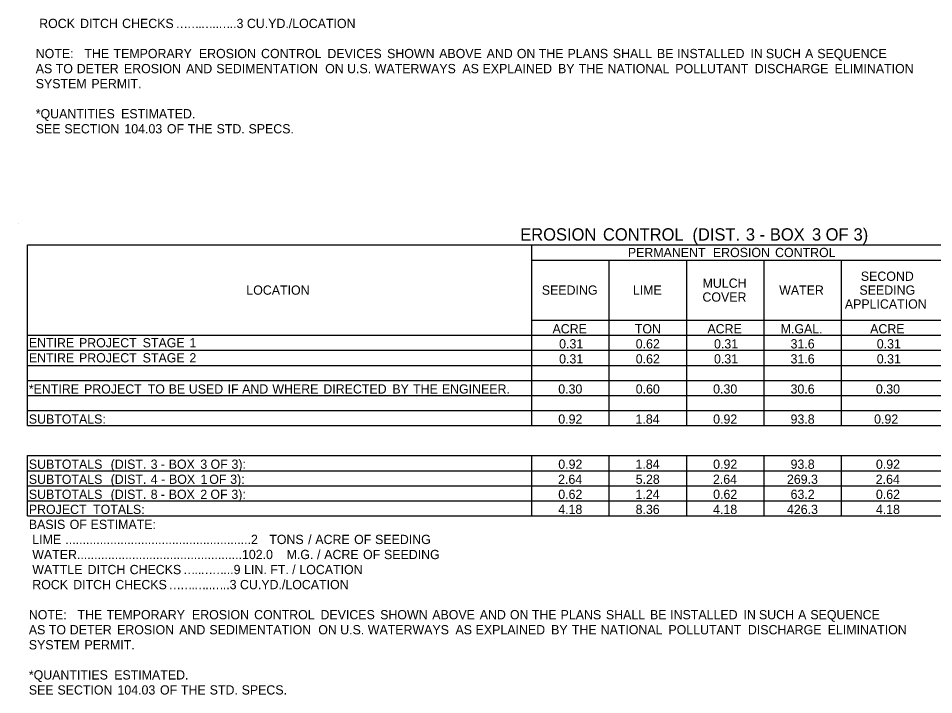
# Model space of a CAD drawing. Extents: x 540541 to 1930787, y -1948574 to 596640.
# Drawn here: x 546405 to 546999, y -1948502 to -1948064 of the extents above; entities that cross this region are included whole.
import ezdxf

# ---------------------------------------------------------------- set-up
doc = ezdxf.new("R2010")
doc.units = 0
doc.layers.add('Default', color=7, linetype='Continuous')
doc.layers.add('R_Border', color=7, linetype='Continuous')

msp = doc.modelspace()

# ---------------------------------------------------------------- linework, layer by layer
at = {"layer": 'Default'}
for p, q in [((546411.17, -1948210.49), (547281.84, -1948210.49)), ((546411.17, -1948327.49), (546411.17, -1948210.49)), ((546411.17, -1948327.49), (546411.17, -1948210.49)), ((546738.28, -1948327.49), (546738.28, -1948210.49)), ((546738.28, -1948220.24), (547281.84, -1948220.24)), ((546788.49, -1948327.49), (546788.49, -1948220.24)), ((546838.7, -1948327.49), (546838.7, -1948220.24)), ((546888.92, -1948327.49), (546888.92, -1948220.24)), ((546939.13, -1948327.49), (546939.13, -1948220.24)), ((546738.28, -1948259.24), (547221.88, -1948259.24)), ((546788.49, -1948327.49), (546788.49, -1948259.24)), ((546838.7, -1948317.74), (546838.7, -1948259.24)), ((546888.92, -1948317.74), (546888.92, -1948259.24)), ((546939.13, -1948317.74), (546939.13, -1948259.24)), ((546411.17, -1948268.99), (547281.84, -1948268.99)), ((546411.17, -1948278.74), (547281.84, -1948278.74)), ((546411.17, -1948288.49), (547281.84, -1948288.49)), ((546411.17, -1948298.24), (547281.84, -1948298.24)), ((546411.17, -1948307.99), (547281.84, -1948307.99)), ((546411.17, -1948317.74), (547121.94, -1948317.74)), ((546738.28, -1948327.49), (546738.28, -1948317.74)), ((546788.49, -1948317.74), (546999.58, -1948317.74)), ((546411.17, -1948327.49), (547281.84, -1948327.49)), ((546411.17, -1948346.99), (547281.84, -1948346.99)), ((546411.17, -1948346.99), (547281.84, -1948346.99)), ((546411.17, -1948385.99), (546411.17, -1948346.99)), ((546411.17, -1948385.99), (546411.17, -1948346.99)), ((546738.28, -1948385.99), (546738.28, -1948346.99)), ((546738.28, -1948385.99), (546738.28, -1948346.99)), ((546788.49, -1948385.99), (546788.49, -1948346.99)), ((546838.7, -1948385.99), (546838.7, -1948346.99)), ((546888.92, -1948385.99), (546888.92, -1948346.99)), ((546939.13, -1948385.99), (546939.13, -1948346.99)), ((546411.17, -1948356.74), (547281.84, -1948356.74)), ((546788.49, -1948385.99), (546788.49, -1948356.74)), ((546838.7, -1948385.99), (546838.7, -1948356.74)), ((546888.92, -1948385.99), (546888.92, -1948356.74)), ((546939.13, -1948385.99), (546939.13, -1948356.74)), ((546411.17, -1948366.49), (547281.84, -1948366.49)), ((546411.17, -1948376.24), (547281.84, -1948376.24)), ((546411.17, -1948385.99), (547281.84, -1948385.99))]:
    msp.add_line(p, q, dxfattribs=at)
at = {"layer": 'R_Border'}
msp.add_line((546405.32, -1948196.84), (546405.32, -1948196.84), dxfattribs=at)

# ---------------------------------------------------------------- texts
at = {"layer": 'Default'}
for s, height, p in [(' ROCK', 6, (546416.62, -1948069.96)), (' DITCH', 6, (546443.15, -1948069.96)), (' CHECKS', 6, (546470.41, -1948069.96)), ('..3', 6, (546542.36, -1948069.96)), (' CU.YD./LOCATION', 6, (546551.3, -1948069.96)), ('…', 6, (546507.25, -1948069.96)), ('…', 6, (546514.65, -1948069.96)), ('.', 6, (546522.05, -1948069.96)), ('…', 6, (546523.64, -1948069.96)), ('..', 6, (546531.04, -1948069.96)), ('…', 6, (546534.97, -1948069.96)), ('NOTE:', 6, (546416.62, -1948089.46)), ('   THE', 6, (546441.5, -1948089.46)), (' TEMPORARY', 6, (546464.81, -1948089.46)), (' EROSION', 6, (546520.18, -1948089.46)), (' CONTROL', 6, (546560.49, -1948089.46)), (' DEVICES', 6, (546603.51, -1948089.46)), (' SHOWN', 6, (546642.21, -1948089.46)), (' ABOVE', 6, (546675.98, -1948089.46)), (' AND', 6, (546706.76, -1948089.46)), (' ON', 6, (546726.34, -1948089.46)), (' THE', 6, (546740.56, -1948089.46)), (' PLANS', 6, (546759.21, -1948089.46)), (' SHALL', 6, (546788.59, -1948089.46)), (' BE', 6, (546817.18, -1948089.46)), (' INSTALLED', 6, (546830.25, -1948089.46)), (' IN', 6, (546877.78, -1948089.46)), (' SUCH', 6, (546887.81, -1948089.46)), (' A', 6, (546913.22, -1948089.46)), (' SEQUENCE', 6, (546921.15, -1948089.46)), ('AS', 6, (546416.62, -1948099.21)), (' TO', 6, (546427.36, -1948099.21)), (' DETER', 6, (546440.96, -1948099.21)), (' EROSION', 6, (546471.59, -1948099.21)), (' AND', 6, (546511.9, -1948099.21)), (' SEDIMENTATION', 6, (546531.48, -1948099.21)), (' ON', 6, (546602.06, -1948099.21)), (' U.S.', 6, (546616.28, -1948099.21)), (' WATERWAYS', 6, (546634.18, -1948099.21)), (' AS', 6, (546691.03, -1948099.21)), (' EXPLAINED', 6, (546704.11, -1948099.21)), (' BY', 6, (546753.05, -1948099.21)), (' THE', 6, (546766.5, -1948099.21)), (' NATIONAL', 6, (546785.15, -1948099.21)), (' POLLUTANT', 6, (546829.11, -1948099.21)), (' DISCHARGE', 6, (546880.65, -1948099.21)), (' ELIMINATION', 6, (546932.37, -1948099.21)), ('SYSTEM', 6, (546416.62, -1948108.96)), (' PERMIT.', 6, (546450.46, -1948108.96)), ('*QUANTITIES', 6, (546416.62, -1948128.46)), (' ESTIMATED.', 6, (546469.75, -1948128.46)), ('SEE', 6, (546416.62, -1948138.21)), (' SECTION', 6, (546432.95, -1948138.21)), (' 104.03', 6, (546471.86, -1948138.21)), (' OF', 6, (546499.43, -1948138.21)), (' THE', 6, (546513.02, -1948138.21)), (' STD.', 6, (546531.67, -1948138.21)), (' SPECS.', 6, (546552.36, -1948138.21)), ('EROSION', 8, (546730.77, -1948207.66)), (' CONTROL', 8, (546781.43, -1948207.66)), (' (DIST.', 8, (546839.47, -1948207.66)), (' 3', 8, (546874.09, -1948207.66)), (' BOX', 8, (546889.67, -1948207.66)), (' 3', 8, (546916.98, -1948207.66)), (' OF', 8, (546925.82, -1948207.66)), (' 3)', 8, (546943.93, -1948207.66)), (' -', 8, (546882.92, -1948207.66)), ('PERMANENT', 6, (546800.54, -1948218.36)), (' EROSION', 6, (546853.47, -1948218.36)), (' CONTROL', 6, (546893.79, -1948218.36)), ('MULCH', 6, (546849, -1948238.24)), ('SECOND', 6, (546951.63, -1948233.74)), ('LOCATION', 6, (546553.17, -1948242.74)), ('SEEDING', 6, (546744.77, -1948242.74)), ('LIME', 6, (546803.79, -1948242.74)), ('WATER', 6, (546898.68, -1948242.74)), ('SEEDING', 6, (546950.74, -1948242.74)), ('COVER', 6, (546848.92, -1948247.24)), ('APPLICATION', 6, (546941.28, -1948251.74)), ('ACRE', 6, (546751.71, -1948267.79)), ('TON', 6, (546805.09, -1948267.79)), ('ACRE', 6, (546852.14, -1948267.79)), ('M.GAL.', 6, (546899.64, -1948267.79)), ('ACRE', 6, (546957.68, -1948267.79)), ('ENTIRE', 6, (546412.14, -1948276.86)), (' PROJECT', 6, (546442.44, -1948276.86)), (' STAGE', 6, (546483.73, -1948276.86)), (' 1', 6, (546514.03, -1948276.86)), ('0.31', 6, (546756, -1948277.54)), ('0.62', 6, (546805.67, -1948277.54)), ('0.31', 6, (546856.43, -1948277.54)), ('31.6', 6, (546906.06, -1948277.54)), ('0.31', 6, (546961.97, -1948277.54)), ('ENTIRE', 6, (546412.14, -1948286.61)), (' PROJECT', 6, (546442.44, -1948286.61)), (' STAGE', 6, (546483.73, -1948286.61)), (' 2', 6, (546514.03, -1948286.61)), ('0.31', 6, (546756, -1948287.29)), ('0.62', 6, (546805.67, -1948287.29)), ('0.31', 6, (546856.43, -1948287.29)), ('31.6', 6, (546906.06, -1948287.29)), ('0.31', 6, (546961.97, -1948287.29)), ('*ENTIRE', 6, (546412.14, -1948306.79)), (' PROJECT', 6, (546445.7, -1948306.79)), (' TO', 6, (546486.99, -1948306.79)), (' BE', 6, (546500.59, -1948306.79)), (' USED', 6, (546513.65, -1948306.79)), (' IF', 6, (546538.83, -1948306.79)), (' AND', 6, (546548.22, -1948306.79)), (' WHERE', 6, (546567.8, -1948306.79)), (' DIRECTED', 6, (546600.89, -1948306.79)), (' BY', 6, (546645.62, -1948306.79)), (' THE', 6, (546659.07, -1948306.79)), (' ENGINEER.', 6, (546677.72, -1948306.79)), ('0.30', 6, (546755.43, -1948306.79)), ('0.60', 6, (546805.65, -1948306.79)), ('0.30', 6, (546855.86, -1948306.79)), ('30.6', 6, (546906.06, -1948306.79)), ('0.30', 6, (546961.4, -1948306.79)), ('SUBTOTALS:', 6, (546412.14, -1948326.29)), ('0.92', 6, (546755.44, -1948326.29)), ('1.84', 6, (546805.54, -1948326.29)), ('0.92', 6, (546855.87, -1948326.29)), ('93.8', 6, (546906.06, -1948326.29)), ('0.92', 6, (546960.25, -1948326.29)), ('SUBTOTALS', 6, (546412.14, -1948355.54)), (' (DIST.', 6, (546462.97, -1948355.54)), (' 3', 6, (546488.93, -1948355.54)), (' BOX', 6, (546500.62, -1948355.54)), (' 3', 6, (546521.11, -1948355.54)), (' OF', 6, (546527.73, -1948355.54)), (' 3):', 6, (546541.32, -1948355.54)), ('0.92', 6, (546755.44, -1948355.54)), ('1.84', 6, (546805.54, -1948355.54)), ('0.92', 6, (546855.87, -1948355.54)), ('93.8', 6, (546906.06, -1948355.54)), ('0.92', 6, (546961.41, -1948355.54)), (' -', 6, (546495.56, -1948355.54)), ('SUBTOTALS', 6, (546412.14, -1948365.29)), (' (DIST.', 6, (546462.97, -1948365.29)), (' 4', 6, (546488.93, -1948365.29)), (' -', 6, (546495.73, -1948365.29)), (' BOX', 6, (546500.79, -1948365.29)), (' 1', 6, (546521.28, -1948365.29)), (' OF', 6, (546526.91, -1948365.29)), (' 3):', 6, (546540.49, -1948365.29)), ('2.64', 6, (546755.33, -1948365.29)), ('5.28', 6, (546805.63, -1948365.29)), ('2.64', 6, (546855.75, -1948365.29)), ('269.3', 6, (546903.72, -1948365.29)), ('2.64', 6, (546961.3, -1948365.29)), ('SUBTOTALS', 6, (546412.14, -1948375.04)), (' (DIST.', 6, (546462.97, -1948375.04)), (' 8', 6, (546488.93, -1948375.04)), (' BOX', 6, (546500.61, -1948375.04)), (' 2', 6, (546521.09, -1948375.04)), (' OF', 6, (546527.66, -1948375.04)), (' 3):', 6, (546541.24, -1948375.04)), ('0.62', 6, (546755.44, -1948375.04)), ('1.24', 6, (546805.54, -1948375.04)), ('0.62', 6, (546855.87, -1948375.04)), ('63.2', 6, (546906.08, -1948375.04)), ('0.62', 6, (546961.41, -1948375.04)), (' -', 6, (546495.55, -1948375.04)), ('PROJECT', 6, (546412.14, -1948384.79)), (' TOTALS:', 6, (546451.57, -1948384.79)), ('4.18', 6, (546755.42, -1948384.79)), ('8.36', 6, (546805.59, -1948384.79)), ('4.18', 6, (546855.84, -1948384.79)), ('426.3', 6, (546903.72, -1948384.79)), ('4.18', 6, (546961.39, -1948384.79)), ('BASIS', 6, (546412.14, -1948394.54)), (' OF', 6, (546436.4, -1948394.54)), (' ESTIMATE:', 6, (546449.99, -1948394.54)), (' LIME', 6, (546412.14, -1948404.29)), (' ......................................................2', 6, (546433.59, -1948404.29)), (' TONS', 6, (546565.83, -1948404.29)), (' /', 6, (546591.01, -1948404.29)), (' ACRE', 6, (546595.67, -1948404.29)), (' OF', 6, (546620.84, -1948404.29)), (' SEEDING', 6, (546634.43, -1948404.29)), (' WATER................................................102.0', 6, (546412.14, -1948414.04)), (' M.G.', 6, (546577.04, -1948414.04)), (' /', 6, (546596.8, -1948414.04)), (' ACRE', 6, (546601.46, -1948414.04)), (' OF', 6, (546626.63, -1948414.04)), (' SEEDING', 6, (546640.22, -1948414.04)), (' WATTLE', 6, (546412.14, -1948423.79)), (' DITCH', 6, (546448.02, -1948423.79)), (' CHECKS', 6, (546475.29, -1948423.79)), ('…', 6, (546512.12, -1948423.79)), ('..', 6, (546519.52, -1948423.79)), ('…', 6, (546523.44, -1948423.79)), ('…', 6, (546530.84, -1948423.79)), ('...9', 6, (546538.24, -1948423.79)), (' LIN.', 6, (546549.52, -1948423.79)), (' FT.', 6, (546566.48, -1948423.79)), (' /', 6, (546580.65, -1948423.79)), (' LOCATION', 6, (546585.31, -1948423.79)), (' ROCK', 6, (546412.14, -1948433.54)), (' DITCH', 6, (546438.68, -1948433.54)), (' CHECKS', 6, (546465.94, -1948433.54)), ('..3', 6, (546537.89, -1948433.54)), (' CU.YD./LOCATION', 6, (546546.83, -1948433.54)), ('…', 6, (546502.77, -1948433.54)), ('…', 6, (546510.17, -1948433.54)), ('.', 6, (546517.57, -1948433.54)), ('…', 6, (546519.17, -1948433.54)), ('..', 6, (546526.57, -1948433.54)), ('…', 6, (546530.49, -1948433.54)), ('NOTE:', 6, (546412.14, -1948453.04)), ('   THE', 6, (546437.03, -1948453.04)), (' TEMPORARY', 6, (546460.33, -1948453.04)), (' EROSION', 6, (546515.71, -1948453.04)), (' CONTROL', 6, (546556.01, -1948453.04)), (' DEVICES', 6, (546599.03, -1948453.04)), (' SHOWN', 6, (546637.73, -1948453.04)), (' ABOVE', 6, (546671.51, -1948453.04)), (' AND', 6, (546702.28, -1948453.04)), (' ON', 6, (546721.86, -1948453.04)), (' THE', 6, (546736.08, -1948453.04)), (' PLANS', 6, (546754.73, -1948453.04)), (' SHALL', 6, (546784.11, -1948453.04)), (' BE', 6, (546812.71, -1948453.04)), (' INSTALLED', 6, (546825.77, -1948453.04)), (' IN', 6, (546873.31, -1948453.04)), (' SUCH', 6, (546883.33, -1948453.04)), (' A', 6, (546908.74, -1948453.04)), (' SEQUENCE', 6, (546916.68, -1948453.04)), ('AS', 6, (546412.14, -1948462.79)), (' TO', 6, (546422.89, -1948462.79)), (' DETER', 6, (546436.48, -1948462.79)), (' EROSION', 6, (546467.12, -1948462.79)), (' AND', 6, (546507.42, -1948462.79)), (' SEDIMENTATION', 6, (546527.01, -1948462.79)), (' ON', 6, (546597.59, -1948462.79)), (' U.S.', 6, (546611.81, -1948462.79)), (' WATERWAYS', 6, (546629.71, -1948462.79)), (' AS', 6, (546686.56, -1948462.79)), (' EXPLAINED', 6, (546699.63, -1948462.79)), (' BY', 6, (546748.58, -1948462.79)), (' THE', 6, (546762.03, -1948462.79)), (' NATIONAL', 6, (546780.68, -1948462.79)), (' POLLUTANT', 6, (546824.63, -1948462.79)), (' DISCHARGE', 6, (546876.17, -1948462.79)), (' ELIMINATION', 6, (546927.9, -1948462.79)), ('SYSTEM', 6, (546412.14, -1948472.54)), (' PERMIT.', 6, (546445.99, -1948472.54)), ('*QUANTITIES', 6, (546412.14, -1948492.04)), (' ESTIMATED.', 6, (546465.27, -1948492.04)), ('SEE', 6, (546412.14, -1948501.79)), (' SECTION', 6, (546428.47, -1948501.79)), (' 104.03', 6, (546467.38, -1948501.79)), (' OF', 6, (546494.96, -1948501.79)), (' THE', 6, (546508.54, -1948501.79)), (' STD.', 6, (546527.19, -1948501.79)), (' SPECS.', 6, (546547.89, -1948501.79))]:
    msp.add_text(s, height=height, dxfattribs=at).set_placement(p)

doc.saveas('drawing.dxf')
